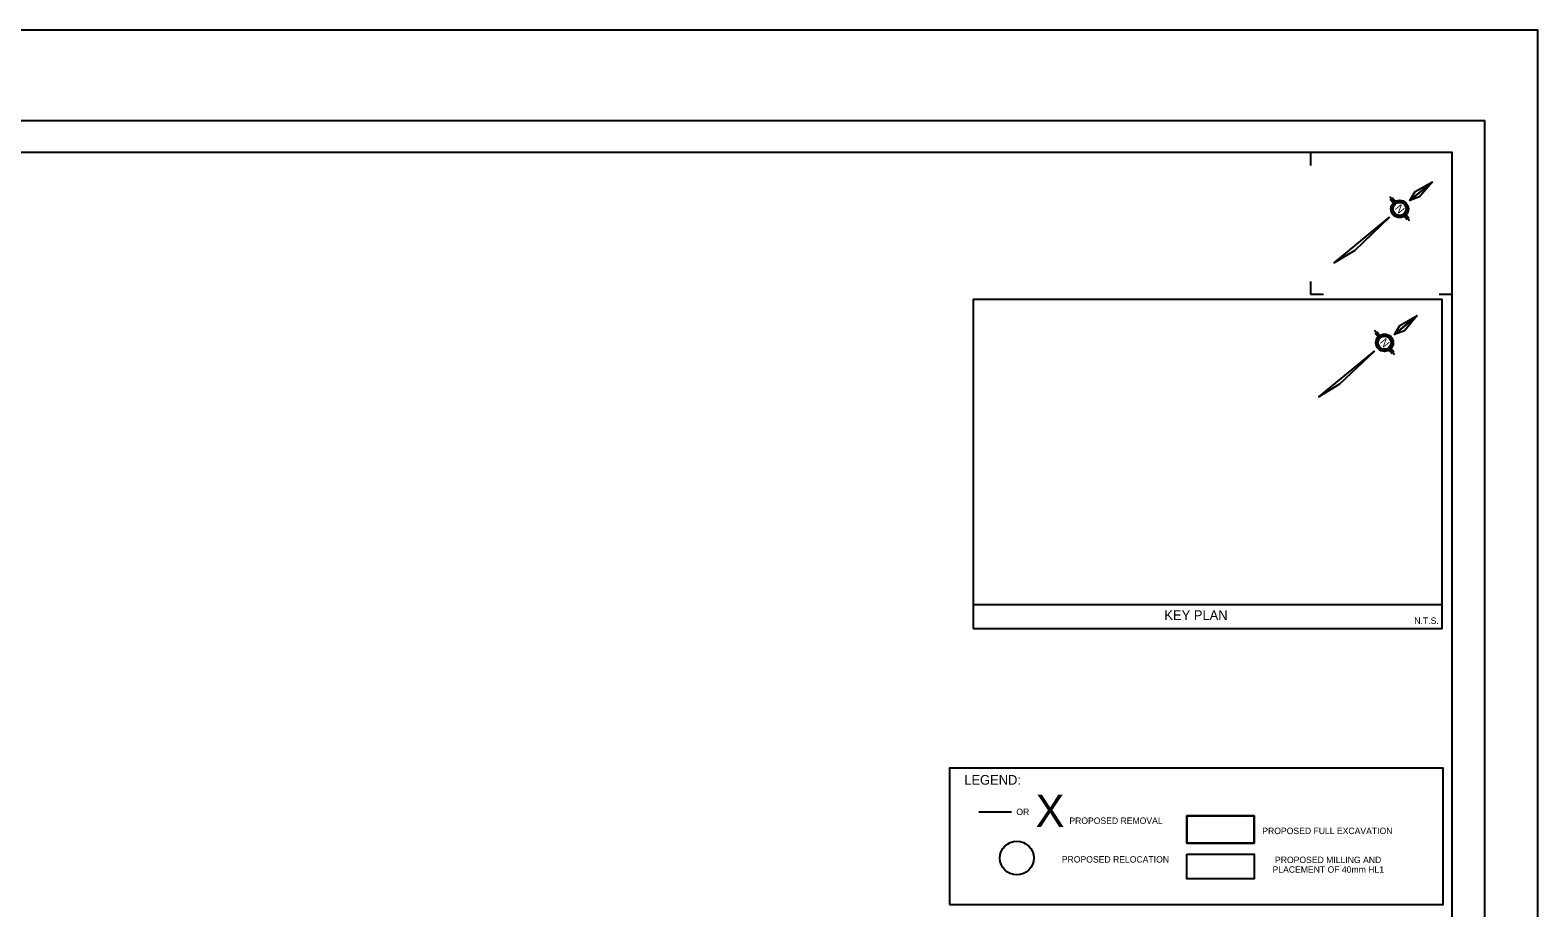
# Model space of a CAD drawing. Extents: x 595568 to 603709, y 4837996 to 4846716.
# Drawn here: x 603142.9 to 603377, y 4846509.4 to 4846645.6 of the extents above; entities that cross this region are included whole.
import ezdxf

# ---------------------------------------------------------------- set-up
doc = ezdxf.new("R2010")
doc.units = 0
for name, color, linetype in [('-PRINT FULLSIZE', 7, 'Continuous'), ('-PRINT HALFSIZE', 7, 'Continuous'), ('ENG_BORDER', 7, 'Continuous'), ('ENG_KEY', 7, 'Continuous'), ('ENG_LEGEND', 7, 'Continuous'), ('ENG_REMOVALS', 7, 'Continuous'), ('ENG_REMOVALS-LINEAR', 7, 'Continuous'), ('ENG_REMOVALS-RELOCATE', 7, 'Continuous'), ('ENG_SH_ASPHALT', 7, 'Continuous'), ('ENG_SH_CONCRETE', 7, 'Continuous'), ('ENG_TITLEBLOCK', 7, 'Continuous'), ('ENG_TX_LEGEND', 7, 'Continuous'), ('ENG_TX_REMOVALS', 7, 'Continuous')]:
    doc.layers.add(name, color=color, linetype=linetype)

msp = doc.modelspace()

# ---------------------------------------------------------------- linework, layer by layer
at = {"layer": '-PRINT FULLSIZE'}
msp.add_lwpolyline([(602930, 4846340.65), (603377.03, 4846340.65), (603377.03, 4846645.65), (602930, 4846645.65)], close=True, dxfattribs=at)
at = {"layer": '-PRINT HALFSIZE'}
msp.add_lwpolyline([(602959.8, 4846631.64), (603368.72, 4846631.64), (603368.72, 4846352.64), (602959.8, 4846352.64)], close=True, dxfattribs=at)
at = {"layer": 'ENG_BORDER'}
msp.add_lwpolyline([(602975.52, 4846357.64), (603363.72, 4846357.64), (603363.72, 4846626.64), (602975.52, 4846626.64)], close=True, dxfattribs=at)
at = {"layer": 'ENG_KEY'}
for p, q in [((603352.36, 4846598.15), (603351.67, 4846598.99)), ((603352.23, 4846598.03), (603351.77, 4846598.59)), ((603352.51, 4846598.26), (603352.04, 4846598.82)), ((603354.39, 4846595.41), (603353.93, 4846595.97)), ((603354.77, 4846595.24), (603354.08, 4846596.07)), ((603354.67, 4846595.64), (603354.21, 4846596.2)), ((603289.33, 4846556.44), (603362.15, 4846556.44))]:
    msp.add_line(p, q, dxfattribs=at)
for points in [[(603289.33, 4846552.76), (603362.15, 4846552.76), (603362.15, 4846603.82), (603289.33, 4846603.82)], [(603358.31, 4846601.32), (603356.3, 4846598.96), (603354.79, 4846598.41)], [(603358.31, 4846601.32), (603354.79, 4846598.41), (603355.62, 4846599.8)], [(603351.65, 4846595.81), (603346.25, 4846590.66), (603343.04, 4846588.71)]]:
    msp.add_lwpolyline(points, close=True, dxfattribs=at)
for radius in [1.35, 1.25, 1.01]:
    msp.add_circle((603353.22, 4846597.11), radius, dxfattribs=at)
at = {"layer": 'ENG_LEGEND'}
msp.add_lwpolyline([(603285.69, 4846509.86), (603362.31, 4846509.86), (603362.31, 4846531.05), (603285.69, 4846531.05)], close=True, dxfattribs=at)
at = {"layer": 'ENG_REMOVALS'}
msp.add_lwpolyline([(603322.51, 4846519.42), (603332.98, 4846519.42), (603332.98, 4846523.67), (603322.51, 4846523.67)], close=True, dxfattribs=at)
at = {"layer": 'ENG_REMOVALS-LINEAR'}
msp.add_line((603290.23, 4846524.27), (603295.3, 4846524.27), dxfattribs=at)
at = {"layer": 'ENG_REMOVALS-RELOCATE'}
msp.add_circle((603296.12, 4846517.09), 2.62, dxfattribs=at)
at = {"layer": 'ENG_SH_ASPHALT'}
msp.add_lwpolyline([(603322.51, 4846523.67), (603332.98, 4846523.67), (603332.98, 4846519.42), (603322.51, 4846519.42)], close=True, dxfattribs=at)
at = {"layer": 'ENG_SH_CONCRETE'}
msp.add_lwpolyline([(603322.51, 4846517.72), (603332.98, 4846517.72), (603332.98, 4846513.87), (603322.51, 4846513.87)], close=True, dxfattribs=at)
at = {"layer": 'ENG_TITLEBLOCK'}
for p, q in [((603341.72, 4846626.64), (603341.72, 4846624.64)), ((603354.71, 4846618.93), (603354.02, 4846619.77)), ((603354.58, 4846618.81), (603354.11, 4846619.37)), ((603354.85, 4846619.04), (603354.39, 4846619.6)), ((603356.74, 4846616.19), (603356.28, 4846616.75)), ((603357.11, 4846616.02), (603356.43, 4846616.85)), ((603357.02, 4846616.42), (603356.56, 4846616.98)), ((603341.72, 4846606.64), (603341.72, 4846604.64)), ((603341.72, 4846604.64), (603343.72, 4846604.64)), ((603361.72, 4846604.64), (603363.72, 4846604.64))]:
    msp.add_line(p, q, dxfattribs=at)
for points in [[(603360.66, 4846622.1), (603358.65, 4846619.74), (603357.14, 4846619.19)], [(603360.66, 4846622.1), (603357.14, 4846619.19), (603357.97, 4846620.58)], [(603353.99, 4846616.59), (603348.6, 4846611.44), (603345.39, 4846609.49)]]:
    msp.add_lwpolyline(points, close=True, dxfattribs=at)
for radius in [1.35, 1.25, 1.01]:
    msp.add_circle((603355.57, 4846617.89), radius, dxfattribs=at)

# ---------------------------------------------------------------- texts
at = {"layer": 'ENG_KEY'}
msp.add_text('N', height=1.2, rotation=309.5559, dxfattribs=at).set_placement((603352.43, 4846597.17))
at = {"layer": 'ENG_REMOVALS'}
msp.add_text('X', height=5, rotation=360, dxfattribs=at).set_placement((603299.05, 4846521.93))
at = {"layer": 'ENG_TITLEBLOCK'}
msp.add_text('N', height=1.2, rotation=309.5559, dxfattribs=at).set_placement((603354.77, 4846617.96))
at = {"layer": 'ENG_TX_LEGEND'}
for s, height, p in [('KEY PLAN', 1.5, (603319.04, 4846554.06)), ('N.T.S.', 1, (603357.85, 4846553.45)), ('LEGEND:', 1.5, (603287.96, 4846528.48))]:
    msp.add_text(s, height=height, rotation=360, dxfattribs=at).set_placement(p)
at = {"layer": 'ENG_TX_REMOVALS'}
for s, p in [('OR', (603296.05, 4846523.77)), ('PROPOSED REMOVAL', (603304.28, 4846522.39)), ('PROPOSED FULL EXCAVATION', (603334.24, 4846520.81)), ('PROPOSED RELOCATION', (603303.11, 4846516.39)), ('PLACEMENT OF 40mm HL1', (603335.83, 4846514.81)), ('PROPOSED MILLING AND', (603336.21, 4846516.31))]:
    msp.add_text(s, height=1, rotation=360, dxfattribs=at).set_placement(p)

doc.saveas('drawing.dxf')
